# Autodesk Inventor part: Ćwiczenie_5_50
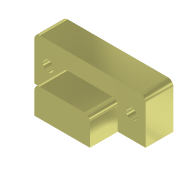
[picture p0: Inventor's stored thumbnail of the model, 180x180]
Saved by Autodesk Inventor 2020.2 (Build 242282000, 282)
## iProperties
Created: 2005-05
Part Number: Ćwiczenie_5_50
Document SubType Name: Modeling
Designer: F.Stasiak
Manufacturer: Standard
Standards Organization: Custom
Density: 1 g/cm^3
Material: Ogólny
Appearance: Nikiel
Manager: www.cadconsulting.pl
Company: Fabian Stasiak CAD Consulting
Author: F.Stasiak
Subject: Zbiór ćwiczeń. Autodesk Inventor 2020. Kurs podstawowy
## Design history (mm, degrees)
sketch "Szkic1"
  geometry: L1 (-100, 50)-(100, 50); L2 (100, 50)-(100, 0); L3 (100, 0)-(-100, 0); L4 (-100, 0)-(-100, 50); 2 further points
  constraints: 8 end point, 2 parallel, 1 coincident, 1 horizontal, 1 midpoint, 1 perpendicular
  dimensions: "d0" = 200 distance of L1.start L1.end; "d1" = 50 distance of L3.end L1.start
extrude "Wyciągnięcie proste1" new body sketch "Szkic1" distance "d2" = 80; taper "d3" = 0 deg
sketch "Szkic2"
  geometry: L1 (100, 0)-(-100, 0) reference; L2 (-50, 0)-(50, 0); L3 (50, 0)-(50, -50); L4 (50, -50)-(-50, -50); L5 (-50, -50)-(-50, 0); 1 further point
  constraints: 8 end point, 2 midpoint, 2 parallel, 1 horizontal, 1 perpendicular
  dimensions: "d4" = 50 distance of L4.end L2.start; "d5" = 100 distance of L3.end L4.end
extrude "Wyciągnięcie proste2" join sketch "Szkic2" distance "d6" = 50; taper "d7" = 0 deg
sketch "Szkic3"
  geometry: L1 (0, -80)-(200, -80) reference; L2 (200, 0)-(200, -80) reference; L3 (0, 0)-(200, 0) reference; L4 (0, 0)-(0, -80) reference; L5 (150, -50)-(150, 0) reference; L6 (50, 0)-(50, -50) reference; L7 (50, -50)-(50, -80); L8 (150, -50)-(150, -80); L9 (200, -80)-(150, 0); L10 (0, -80)-(50, 0); 2 further points
  constraints: 8 end point, 2 midpoint, 2 point on line, 1 parallel, 1 perpendicular
hole "Otwór1" sketch "Szkic3" at (25, -40), (175, -40) diameter "d8" = 20; stored, may be unused: countersink angle "d12" = 90 deg, drill point angle "d14" = 118 deg; dims "d9" = 6, "d10" = 4, "d11" = 2, "d13" = 8
fillet "Zaokrąglenie1" dims "d15" = 10
node "Bryła1"
node "Korpusy bryłowe"
node "Korpusy powierzchniowe"
node "Pętla rzutowana1"
